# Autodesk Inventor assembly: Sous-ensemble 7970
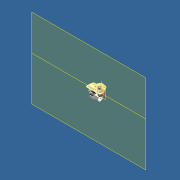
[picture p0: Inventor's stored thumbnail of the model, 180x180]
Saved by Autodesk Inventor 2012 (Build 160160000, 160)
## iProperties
Created: 2011-10
Part Number: Sous-ensemble 7970
Document SubType Name: Assembly
Designer: Laur
Author: Laur
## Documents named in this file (6)
- D:\Formulaire\Sujet CIM 4 Poissy\Modélisation_7970_shimano\Sous-ensemble 7970.iam
- D:\Formulaire\Sujet CIM 4 Poissy\Modélisation_7970_shimano\platine PA-GF inter.ipt
- D:\Formulaire\Sujet CIM 4 Poissy\Modélisation_7970_shimano\cage et arbre-vis sans fin.iam
- D:\Formulaire\Sujet CIM 4 Poissy\Modélisation_7970_shimano\connecteur.ipt
- D:\Formulaire\Sujet CIM 4 Poissy\Modélisation_7970_shimano\contacts connecteur.ipt
- D:\Formulaire\Sujet CIM 4 Poissy\Modélisation_7970_shimano\Butée axiale vis sans fin.ipt
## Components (5 placed, 5 different names)
1. platine PA-GF inter:1 — Angle:1, pos selon axe roue / platine, ENTRAXE roue&vis 10mm, plan de création connecteur, pos2 butée, pos1 butée, pos3 butée, plan de création broches du connecteur, Affleurement:3
2. cage et arbre-vis sans fin:1 [sub-assembly] — Angle:1, pos selon axe roue / platine, ENTRAXE roue&vis 10mm
3. connecteur:1 — plan de création connecteur, Affleurement:3
4. contacts connecteur:1 — plan de création broches du connecteur
5. Butée axiale vis sans fin:1 — pos2 butée, pos1 butée, pos3 butée
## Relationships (9: Mate 5, Flush 3, Angle 1)
- Angle:1: platine PA-GF inter:1 ↔ cage et arbre-vis sans fin:1
- pos selon axe roue / platine [Mate]: platine PA-GF inter:1 ↔ cage et arbre-vis sans fin:1
- ENTRAXE roue&vis 10mm [Mate]: platine PA-GF inter:1 ↔ cage et arbre-vis sans fin:1
- plan de création connecteur [Flush]: platine PA-GF inter:1 ↔ connecteur:1
- plan de création broches du connecteur [Flush]: platine PA-GF inter:1 ↔ contacts connecteur:1
- pos2 butée [Mate]: platine PA-GF inter:1 ↔ Butée axiale vis sans fin:1
- pos1 butée [Mate]: platine PA-GF inter:1 ↔ Butée axiale vis sans fin:1
- pos3 butée [Mate]: platine PA-GF inter:1 ↔ Butée axiale vis sans fin:1
- Affleurement:3 [Flush]: platine PA-GF inter:1 ↔ connecteur:1
